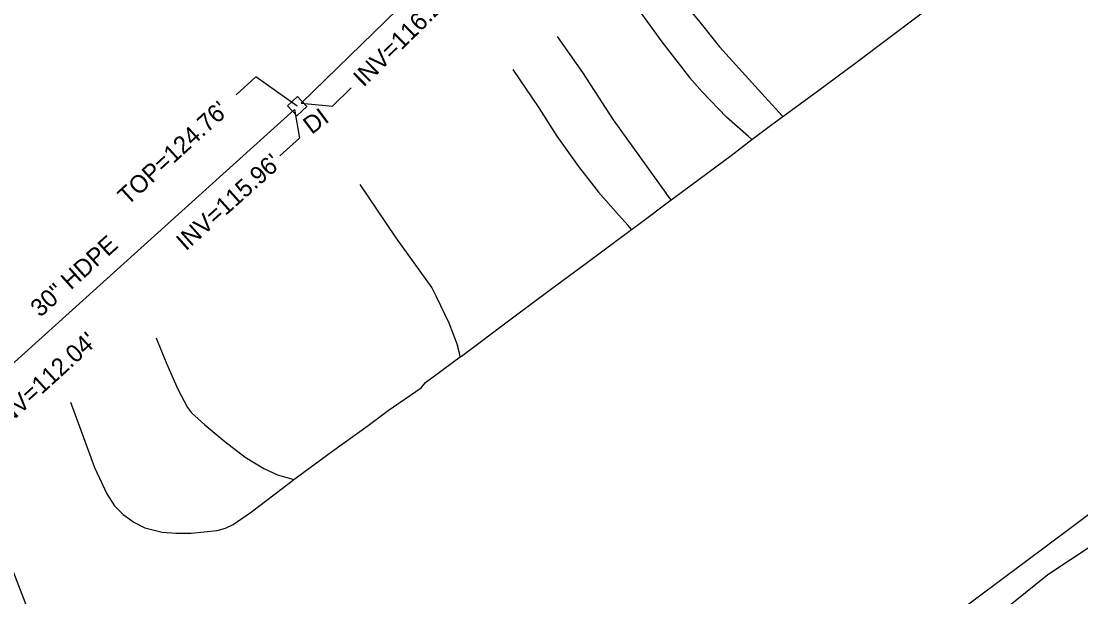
# Model space of a CAD drawing. Extents: x 2186615 to 2188822, y 629899 to 631820.
# Drawn here: x 2187814 to 2188055, y 631112.9 to 631243.8 of the extents above; entities that cross this region are included whole.
import ezdxf

# ---------------------------------------------------------------- set-up
doc = ezdxf.new("R2010")
doc.units = 0
for name, color, linetype in [('Exist Roads EOP Other', 7, 'Continuous'), ('Exist Roads Soil', 7, 'Continuous'), ('Exist Structure Minor Drop Inlet', 7, 'Continuous'), ('Exist Structure Minor Drop Inlet Leader', 7, 'Continuous'), ('Exist Structure Minor Drop Inlet Text', 7, 'Continuous'), ('Exist Structure Minor Drop Inlet Top Elevation', 7, 'Continuous'), ('Exist Structure Minor Pipes HDPE 30 Inch', 7, 'Continuous'), ('Exist Structure Minor Pipes HDPE 30 Inch Invert', 7, 'Continuous'), ('Exist Structure Minor Pipes HDPE 30 Inch Leader', 7, 'Continuous'), ('Exist Structure Minor Pipes HDPE 30 Inch Text', 7, 'Continuous'), ('Exist Vegetation Hedge Row', 7, 'Continuous')]:
    doc.layers.add(name, color=color, linetype=linetype)

msp = doc.modelspace()

# ---------------------------------------------------------------- linework, layer by layer
at = {"layer": 'Exist Roads EOP Other'}
for points in [[(2187987.21, 631222.12), (2187995.13, 631227.9), (2188003.91, 631234.45), (2188018.62, 631245.53), (2188023.39, 631249.04)], [(2187980.23, 631216.9), (2187984.42, 631220.08), (2187987.21, 631222.12)], [(2187961.85, 631203.19), (2187962.7, 631203.83), (2187975.46, 631213.29), (2187980.23, 631216.9)], [(2187952.85, 631196.44), (2187954.49, 631197.66), (2187961.85, 631203.19)], [(2187934.69, 631182.99), (2187935.83, 631183.85), (2187942.75, 631188.91), (2187952.85, 631196.44)], [(2187835.99, 631057.2), (2187832.38, 631066.61), (2187829.78, 631073.37), (2187827.33, 631079.65), (2187823.24, 631090.34), (2187818.48, 631102.46), (2187814.66, 631112.43), (2187811.6, 631120.28), (2187807.65, 631130.42), (2187803.81, 631140.26), (2187800.02, 631150.43), (2187796.16, 631160.6), (2187794.84, 631164.12), (2187792.02, 631171.25), (2187785.09, 631189.07)], [(2187913.88, 631167.44), (2187914.14, 631167.63), (2187925.48, 631176.12), (2187934.69, 631182.99)], [(2187876.05, 631139.55), (2187884.57, 631145.84), (2187892.94, 631151.82), (2187897.47, 631155.28), (2187904.98, 631160.45), (2187906.01, 631161.67), (2187913.88, 631167.44)], [(2187825.27, 631157.2), (2187827.32, 631151.63), (2187828.22, 631149.12)], [(2187828.22, 631149.12), (2187830.72, 631142.31), (2187833.47, 631136.3), (2187835.25, 631133.57), (2187837.21, 631131.58)], [(2187866.39, 631132.21), (2187874.99, 631138.76), (2187876.05, 631139.55)], [(2188066.8, 631139.05), (2188053.17, 631128.89), (2188041.82, 631120.35), (2188026.58, 631108.99)], [(2187837.21, 631131.58), (2187839.65, 631129.83), (2187842.15, 631128.58), (2187846.06, 631127.58), (2187849.38, 631127.35), (2187852.66, 631127.35), (2187858.57, 631127.98), (2187860.51, 631128.46), (2187862.27, 631129.34), (2187866.39, 631132.21)]]:
    msp.add_lwpolyline(points, dxfattribs=at)
at = {"layer": 'Exist Roads Soil'}
for p, q in [((2187961.85, 631203.19), (2187960.71, 631204.67)), ((2187952.85, 631196.44), (2187952.06, 631197.33)), ((2187872.31, 631140.65), (2187876.05, 631139.55))]:
    msp.add_line(p, q, dxfattribs=at)
for points in [[(2187957.89, 631256.91), (2187958.03, 631256.71), (2187961.34, 631252.19), (2187968.34, 631243.62), (2187972.88, 631238), (2187983.14, 631226.62), (2187985.66, 631223.9)], [(2187950.61, 631251.43), (2187955.1, 631245.5), (2187959.71, 631239.11), (2187966.05, 631231), (2187968.92, 631227.74), (2187974.42, 631221.97)], [(2187935.89, 631240.37), (2187941.66, 631232.19), (2187948.65, 631221.42), (2187960.71, 631204.67)], [(2187925.87, 631232.83), (2187931.72, 631224.15), (2187935.87, 631217.67), (2187940.74, 631210.81), (2187945.29, 631204.96), (2187949.84, 631199.81), (2187952.06, 631197.33)], [(2187985.66, 631223.9), (2187987.1, 631222.33), (2187987.21, 631222.12)], [(2187980.23, 631216.9), (2187979.41, 631217.63), (2187974.42, 631221.97)], [(2187891.08, 631206.67), (2187892.97, 631203.84), (2187899.27, 631194.57), (2187907.42, 631183.14), (2187908.43, 631181.22), (2187911.32, 631175.2), (2187913.23, 631170.05)], [(2187844.69, 631171.8), (2187844.79, 631171.54)], [(2187844.79, 631171.54), (2187845.75, 631169.14), (2187847.15, 631165.79), (2187849.65, 631160.09), (2187851.89, 631155.95), (2187852.77, 631154.75), (2187855.76, 631151.98), (2187860.37, 631148.19), (2187864.98, 631144.65), (2187869.24, 631142.05), (2187872.31, 631140.65)], [(2187913.88, 631167.44), (2187913.69, 631168.33), (2187913.23, 631170.05)]]:
    msp.add_lwpolyline(points, dxfattribs=at)
at = {"layer": 'Exist Structure Minor Drop Inlet'}
msp.add_lwpolyline([(2187876.7, 631222.28), (2187879.02, 631224.45), (2187876.88, 631226.73), (2187874.57, 631224.57)], close=True, dxfattribs=at)
at = {"layer": 'Exist Structure Minor Drop Inlet Leader'}
msp.add_lwpolyline([(2187876.8, 631224.48), (2187867.38, 631231.16), (2187862.95, 631227.11)], dxfattribs=at)
at = {"layer": 'Exist Structure Minor Pipes HDPE 30 Inch'}
for p, q in [((2187877.7, 631225.15), (2188023.53, 631367.63)), ((2187780.64, 631137.62), (2187876.22, 631223.72))]:
    msp.add_line(p, q, dxfattribs=at)
at = {"layer": 'Exist Structure Minor Pipes HDPE 30 Inch Leader'}
for points in [[(2187877.7, 631225.15), (2187884.82, 631224.48), (2187889.09, 631228.69)], [(2187876.22, 631223.72), (2187877.35, 631217.24), (2187872.88, 631213.24)]]:
    msp.add_lwpolyline(points, dxfattribs=at)
at = {"layer": 'Exist Vegetation Hedge Row'}
msp.add_lwpolyline([(2188034.66, 631107.54), (2188047.53, 631117.93), (2188057.82, 631124.78)], dxfattribs=at)

# ---------------------------------------------------------------- texts
at = {"layer": 'Exist Structure Minor Drop Inlet Text'}
msp.add_text('DI', height=4, rotation=36.8593, dxfattribs=at).set_placement((2187880.08, 631217.95))
at = {"layer": 'Exist Structure Minor Drop Inlet Top Elevation'}
msp.add_text("TOP=124.76'", height=4, rotation=42.4864, dxfattribs=at).set_placement((2187838.25, 631201.77))
at = {"layer": 'Exist Structure Minor Pipes HDPE 30 Inch Invert'}
for s, rotation, p in [("INV=116.25'", 44.5689, (2187891.92, 631228.67)), ("INV=115.96'", 41.8235, (2187851.51, 631191.43)), ("INV=112.04'", 42.3969, (2187809.78, 631150.67))]:
    msp.add_text(s, height=4, rotation=rotation, dxfattribs=at).set_placement(p)
at = {"layer": 'Exist Structure Minor Pipes HDPE 30 Inch Text'}
msp.add_text('30" HDPE', height=4, rotation=42.0114, dxfattribs=at).set_placement((2187818.36, 631176.31))

doc.saveas('drawing.dxf')
